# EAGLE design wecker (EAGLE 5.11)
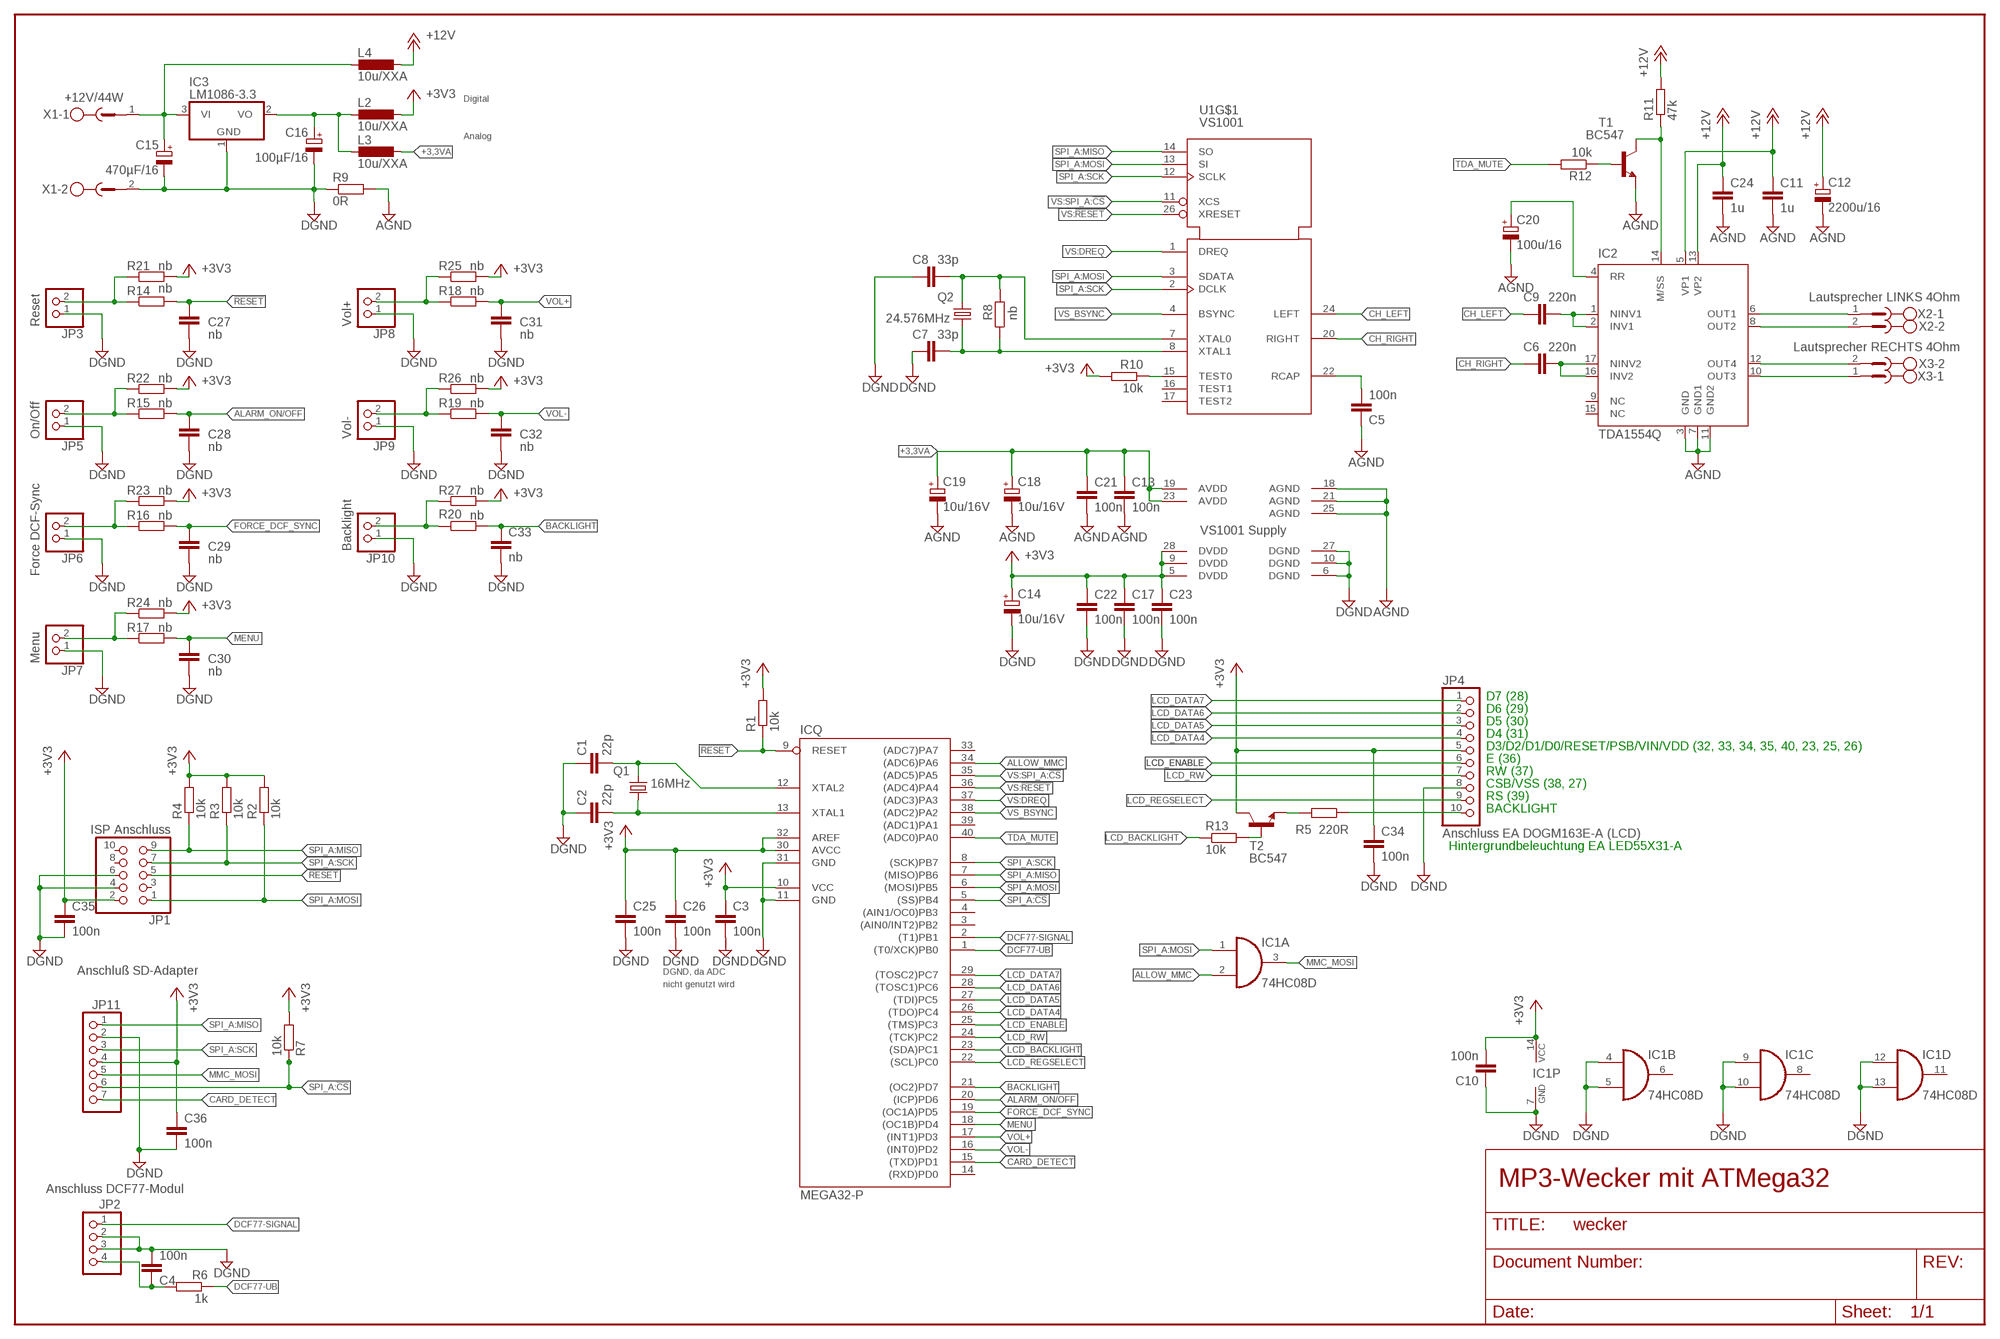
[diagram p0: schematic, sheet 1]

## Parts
C1  22p  C-EUC1206  [C1206]
C2  22p  C-EUC1206  [C1206]
C3  100n  C-EUC1206  [C1206]
C4  100n  C-EUC1206  [C1206]
C5  100n  C-EUC1206K  [C1206K]
C6  220n  C-EUC1206K  [C1206K]
C7  33p  C-EUC1206K  [C1206K]
C8  33p  C-EUC1206K  [C1206K]
C9  220n  C-EUC1206K  [C1206K]
C10  100n  C-EUC1206  [C1206]
C11  1u  C-EUC1206K  [C1206K]
C12  2200u/16  CPOL-EUE5-13  [E5-13]
C13  100n  C-EUC1206K  [C1206K]
C14  10u/16V  CPOL-EUE2,5-6E  [E2,5-6E]
C15  470µF/16  CPOL-EUE5-10.5  [E5-10,5]
C16  100µF/16  CPOL-EUE2,5-6E  [E2,5-6E]
C17  100n  C-EUC1206K  [C1206K]
C18  10u/16V  CPOL-EUE2,5-6E  [E2,5-6E]
C19  10u/16V  CPOL-EUE2,5-6E  [E2,5-6E]
C20  100u/16  CPOL-EUE2,5-6E  [E2,5-6E]
C21  100n  C-EUC1206K  [C1206K]
C22  100n  C-EUC1206K  [C1206K]
C23  100n  C-EUC1206K  [C1206K]
C24  1u  C-EUC1206K  [C1206K]
C25  100n  C-EUC1206  [C1206]
C26  100n  C-EUC1206  [C1206]
C27  nb  C-EUC1206K  [C1206K]
C28  nb  C-EUC1206K  [C1206K]
C29  nb  C-EUC1206K  [C1206K]
C30  nb  C-EUC1206K  [C1206K]
C31  nb  C-EUC1206K  [C1206K]
C32  nb  C-EUC1206K  [C1206K]
C33  nb  C-EUC1206K  [C1206K]
C34  100n  C-EUC1206K  [C1206K]
C35  100n  C-EUC1206K  [C1206K]
C36  100n  C-EUC1206K  [C1206K]
IC1  74HC08D  [SO14]
IC2  TDA1554Q  [MULTIWAT-SIL17]
IC3  LM1086-3.3  [TO220V]
ICQ  MEGA32-P  [DIL40]
JP1  ISP Anschluss  PINHD-2X5  [2X05]
JP2  Anschluss DCF77-Modul  PINHD-1X4  [1X04]
JP3  Reset  PINHD-1X2  [1X02]
JP4  Anschluss EA DOGM163E-A (LCD)  PINHD-1X10  [1X10]
JP5  On/Off  PINHD-1X2  [1X02]
JP6  Force DCF-Sync  PINHD-1X2  [1X02]
JP7  Menu  PINHD-1X2  [1X02]
JP8  Vol+  PINHD-1X2  [1X02]
JP9  Vol-  PINHD-1X2  [1X02]
JP10  Backlight  PINHD-1X2  [1X02]
JP11  Anschluß SD-Adapter  PINHD-1X7  [1X07]
L2  10u/XXA  L-EU0207/10  [0207/10]
L3  10u/XXA  L-EU0207/10  [0207/10]
L4  10u/XXA  L-EU0207/10  [0207/10]
Q1  16MHz  CRYSTALHC49S  [HC49/S]
Q2  24.576MHz  CRYSTALHC49S  [HC49/S]
R1  10k  R-EU_R1206  [R1206]
R2  10k  R-EU_R1206  [R1206]
R3  10k  R-EU_R1206  [R1206]
R4  10k  R-EU_R1206  [R1206]
R5  220R  R-EU_R1206  [R1206]
R6  1k  R-EU_R1206  [R1206]
R7  10k  R-EU_R1206  [R1206]
R8  nb  R-EU_R1206  [R1206]
R9  0R  R-EU_R1206  [R1206]
R10  10k  R-EU_R1206  [R1206]
R11  47k  R-EU_R1206  [R1206]
R12  10k  R-EU_R1206  [R1206]
R13  10k  R-EU_R1206  [R1206]
R14  nb  R-EU_R1206  [R1206]
R15  nb  R-EU_R1206  [R1206]
R16  nb  R-EU_R1206  [R1206]
R17  nb  R-EU_R1206  [R1206]
R18  nb  R-EU_R1206  [R1206]
R19  nb  R-EU_R1206  [R1206]
R20  nb  R-EU_R1206  [R1206]
R21  nb  R-EU_R1206  [R1206]
R22  nb  R-EU_R1206  [R1206]
R23  nb  R-EU_R1206  [R1206]
R24  nb  R-EU_R1206  [R1206]
R25  nb  R-EU_R1206  [R1206]
R26  nb  R-EU_R1206  [R1206]
R27  nb  R-EU_R1206  [R1206]
T1  BC547  [TO92]
T2  BC547  [TO92]
U1  VS1001-SOIC-28  [SO-28L]
X1  +12V/44W  MSTBV2  [MSTBV2]
X2  Lautsprecher LINKS 4Ohm  MSTBV2  [MSTBV2]
X3  Lautsprecher RECHTS 4Ohm  MSTBV2  [MSTBV2]

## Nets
!RESET: C27.1 ICQ.9(RESET) JP1.5 R1.1 R14.2
+3,3VA: C13.1 C18.+ C19.+ C21.1 L3.1 U1.19(AVDD) U1.23(AVDD)
+3V3: C3.1 C10.2 C14.+ C17.1 C22.1 C23.1 C25.1 C26.1 C34.1 C35.1 C36.1 IC1.14(P:VCC) ICQ.10(VCC) ICQ.30(AVCC) ICQ.32(AREF) JP1.2 JP4.5 JP11.4 L2.1 R1.2 R2.2 R3.2 R4.2 R7.2 R10.2 R21.2 R22.2 R23.2 R24.2 R25.2 R26.2 R27.2 T2.3(C) U1.5(DVDD) U1.9(DVDD) U1.28(DVDD)
+12V: C11.1 C12.+ C24.1 IC2.5(VP1) IC2.13(VP2) L4.1 R11.2
+UB: C4.1 JP2.4 R6.2
AGND: C5.1 C11.2 C12.- C13.2 C18.- C19.- C20.- C21.2 C24.2 IC2.3(GND) IC2.7(GND1) IC2.11(GND2) R9.2 T1.1(E) U1.18(AGND) U1.21(AGND) U1.25(AGND)
ALARM_ON/OFF: C28.1 ICQ.20((ICP)PD6) R15.2
ALLOW_MMC: IC1.2(A:I1) ICQ.34((ADC6)PA6)
BACKLIGHT: C33.1 ICQ.21((OC2)PD7) R20.2
BKL: R13.2 T2.2(B)
BKLIGHT: JP4.10 R5.1
CARD_DETECT: ICQ.15((TXD)PD1) JP11.7
CH_LEFT: C9.1 U1.24(LEFT)
CH_RIGHT: C6.1 U1.20(RIGHT)
DCF77-SIGNAL: ICQ.2((T1)PB1) JP2.1
DCF77-UB: ICQ.1((T0/XCK)PB0) R6.1
DGND: C1.1 C2.1 C3.2 C4.2 C7.1 C8.1 C10.1 C14.- C15.- C16.- C17.2 C22.2 C23.2 C25.2 C26.2 C27.2 C28.2 C29.2 C30.2 C31.2 C32.2 C33.2 C34.2 C35.2 C36.2 IC1.4(B:I0) IC1.5(B:I1) IC1.7(P:GND) IC1.9(C:I0) IC1.10(C:I1) IC1.12(D:I0) IC1.13(D:I1) IC3.1(GND) ICQ.11(GND) ICQ.31(GND) JP1.4 JP1.6 JP2.2 JP2.3 JP3.1 JP4.8 JP5.1 JP6.1 JP7.1 JP8.1 JP9.1 JP10.1 JP11.2 R9.1 U1.6(DGND) U1.10(DGND) U1.27(DGND) X1.2
FORCE_DCF_SYNC: C29.1 ICQ.19((OC1A)PD5) R16.2
INPUT_LEFT: C9.2 IC2.1(NINV1) IC2.2(INV1)
INPUT_RIGHT: C6.2 IC2.16(INV2) IC2.17(NINV2)
LCD_BACKLIGHT: ICQ.23((SDA)PC1) R13.1
LCD_DATA4: ICQ.26((TDO)PC4) JP4.4
LCD_DATA5: ICQ.27((TDI)PC5) JP4.3
LCD_DATA6: ICQ.28((TOSC1)PC6) JP4.2
LCD_DATA7: ICQ.29((TOSC2)PC7) JP4.1
LCD_ENABLE: ICQ.25((TMS)PC3) JP4.6
LCD_REGSELECT: ICQ.22((SCL)PC0) JP4.9
LCD_RW: ICQ.24((TCK)PC2) JP4.7
MENU: C30.1 ICQ.18((OC1B)PD4) R17.2
MMC_MOSI: IC1.3(A:O) JP11.5
MP3-TEST0: R10.1 U1.15(TEST0)
MP3-XTAL0: C8.2 Q2.2 R8.2 U1.7(XTAL0)
MP3-XTAL1: C7.2 Q2.1 R8.1 U1.8(XTAL1)
MUTE: IC2.14(M/SS) R11.1 T1.3(C)
N$1: C16.+ IC3.2(VO) L2.2 L3.2
N$2: C15.+ IC3.3(VI) L4.2 X1.1
N$3: R5.2 T2.1(E)
N$4: JP3.2 R14.1 R21.1
N$5: JP5.2 R15.1 R22.1
N$6: JP6.2 R16.1 R23.1
N$7: JP7.2 R17.1 R24.1
N$8: JP8.2 R18.1 R25.1
N$9: JP9.2 R19.1 R26.1
N$10: JP10.2 R20.1 R27.1
OUTPUT_LEFT1: IC2.6(OUT1) X2.1
OUTPUT_LEFT2: IC2.8(OUT2) X2.2
OUTPUT_RIGHT1: IC2.12(OUT4) X3.2
OUTPUT_RIGHT2: IC2.10(OUT3) X3.1
RCAP: C5.2 U1.22(RCAP)
RR: C20.+ IC2.4(RR)
SPI_A:!CS: ICQ.5((SS)PB4) JP11.6 R7.1
SPI_A:MISO: ICQ.7((MISO)PB6) JP1.9 JP11.1 R4.1 U1.14(SO)
SPI_A:MOSI: IC1.1(A:I0) ICQ.6((MOSI)PB5) JP1.1 R2.1 U1.3(SDATA) U1.13(SI)
SPI_A:SCK: ICQ.8((SCK)PB7) JP1.7 JP11.3 R3.1 U1.2(DCLK) U1.12(SCLK)
TDA_MUTE: ICQ.40((ADC0)PA0) R12.2
TDA_MUTE1: R12.1 T1.2(B)
VOL+: C31.1 ICQ.17((INT1)PD3) R18.2
VOL-: C32.1 ICQ.16((INT0)PD2) R19.2
VS:!RESET: ICQ.36((ADC4)PA4) U1.26(XRESET)
VS:DREQ: ICQ.37((ADC3)PA3) U1.1(DREQ)
VS:SPI_A:!CS: ICQ.35((ADC5)PA5) U1.11(XCS)
VS_BSYNC: ICQ.38((ADC2)PA2) U1.4(BSYNC)
XTAL1: C2.2 ICQ.13(XTAL1) Q1.2
XTAL2: C1.2 ICQ.12(XTAL2) Q1.1
Unconnected: IC1.6(B:O) IC1.8(C:O) IC1.11(D:O) IC2.9(NC) IC2.15(NC) ICQ.3((AIN0/INT2)PB2) ICQ.4((AIN1/OC0)PB3) ICQ.14((RXD)PD0) ICQ.33((ADC7)PA7) ICQ.39((ADC1)PA1) JP1.3 JP1.8 JP1.10 U1.16(TEST1) U1.17(TEST2)

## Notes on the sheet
- Digital
- Analog
- D7 (28)
- D6 (29)
- D5 (30)
- D4 (31)
- D3/D2/D1/D0/RESET/PSB/VIN/VDD (32, 33, 34, 35, 40, 23, 25, 26)
- E (36)
- RW (37)
- CSB/VSS (38, 27)
- RS (39)
- BACKLIGHT
- Hintergrundbeleuchtung EA LED55X31-A
- DGND, da ADC
- nicht genutzt wird
- MP3-Wecker mit ATMega32

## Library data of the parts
C1-C11 C13 C17 C21-C36 = rcl:C-EU: CAPACITOR, European symbol
C12 C14-C16 C18-C20 = rcl:CPOL-EU: POLARIZED CAPACITOR, European symbol
IC1 = 74xx-eu:74*08: Quad 2-input AND gate
IC2 = linear2:TDA1554Q: Audio Power Amplifier 4x11W single-ended or 2x22W BTL source: TDA1554Q_CNV.pdf
IC3 = oli:LM1086*: LM1086 1.5A Low Dropout Positive Regulators
ICQ = atmel:MEGA32-P: MICROCONTROLLER 32 Kbytes FLASH 2 Kbytes SRAM 1 Kbytes EEPROM USART 8-channel 10 bit ADC Source: www.atmel.com .. doc2503.pdf
JP1 = pinhead:PINHD-2X5: PIN HEADER
JP2 = pinhead:PINHD-1X4: PIN HEADER
JP3 JP5-JP10 = pinhead:PINHD-1X2: PIN HEADER
JP4 = pinhead:PINHD-1X10: PIN HEADER
JP11 = pinhead:PINHD-1X7: PIN HEADER
L2-L4 = rcl:L-EU: INDUCTOR, European symbol
Q1 Q2 = crystal:CRYSTAL: CRYSTAL
R1-R27 = rcl:R-EU_: RESISTOR, European symbol
T1 T2 = transistor:BC547: NPN TRANSISTOR
U1 = vs1001:VS1001: MP3 decoder chip from VLSI Solutions
X1-X3 = con-phoenix-500:MSTBV2: PHOENIX

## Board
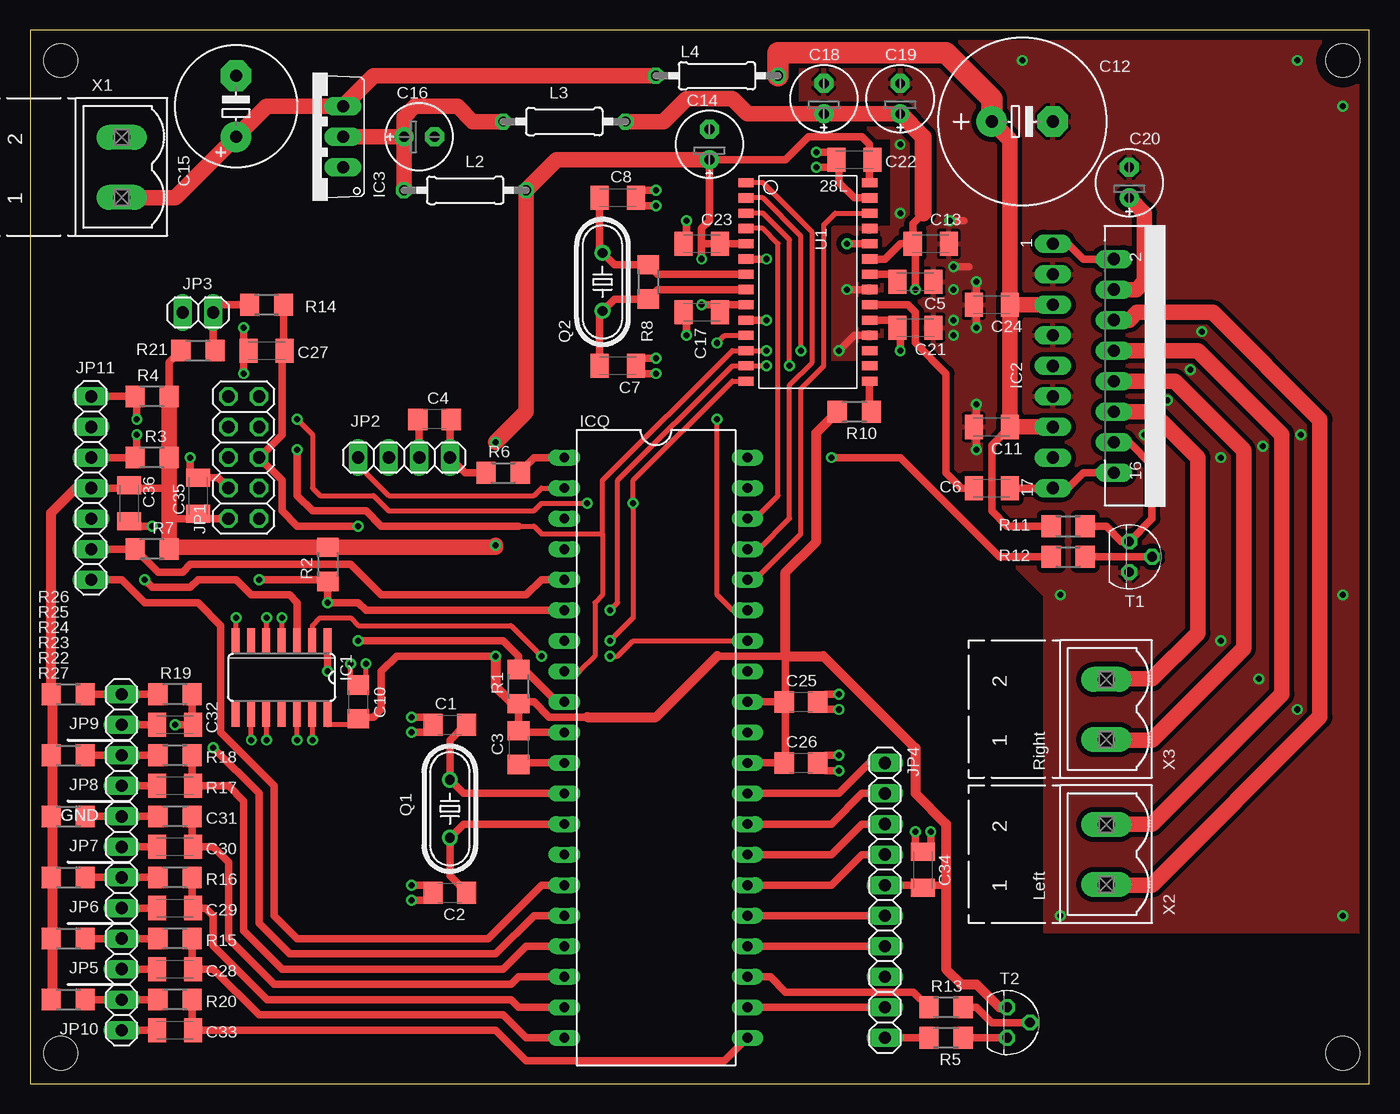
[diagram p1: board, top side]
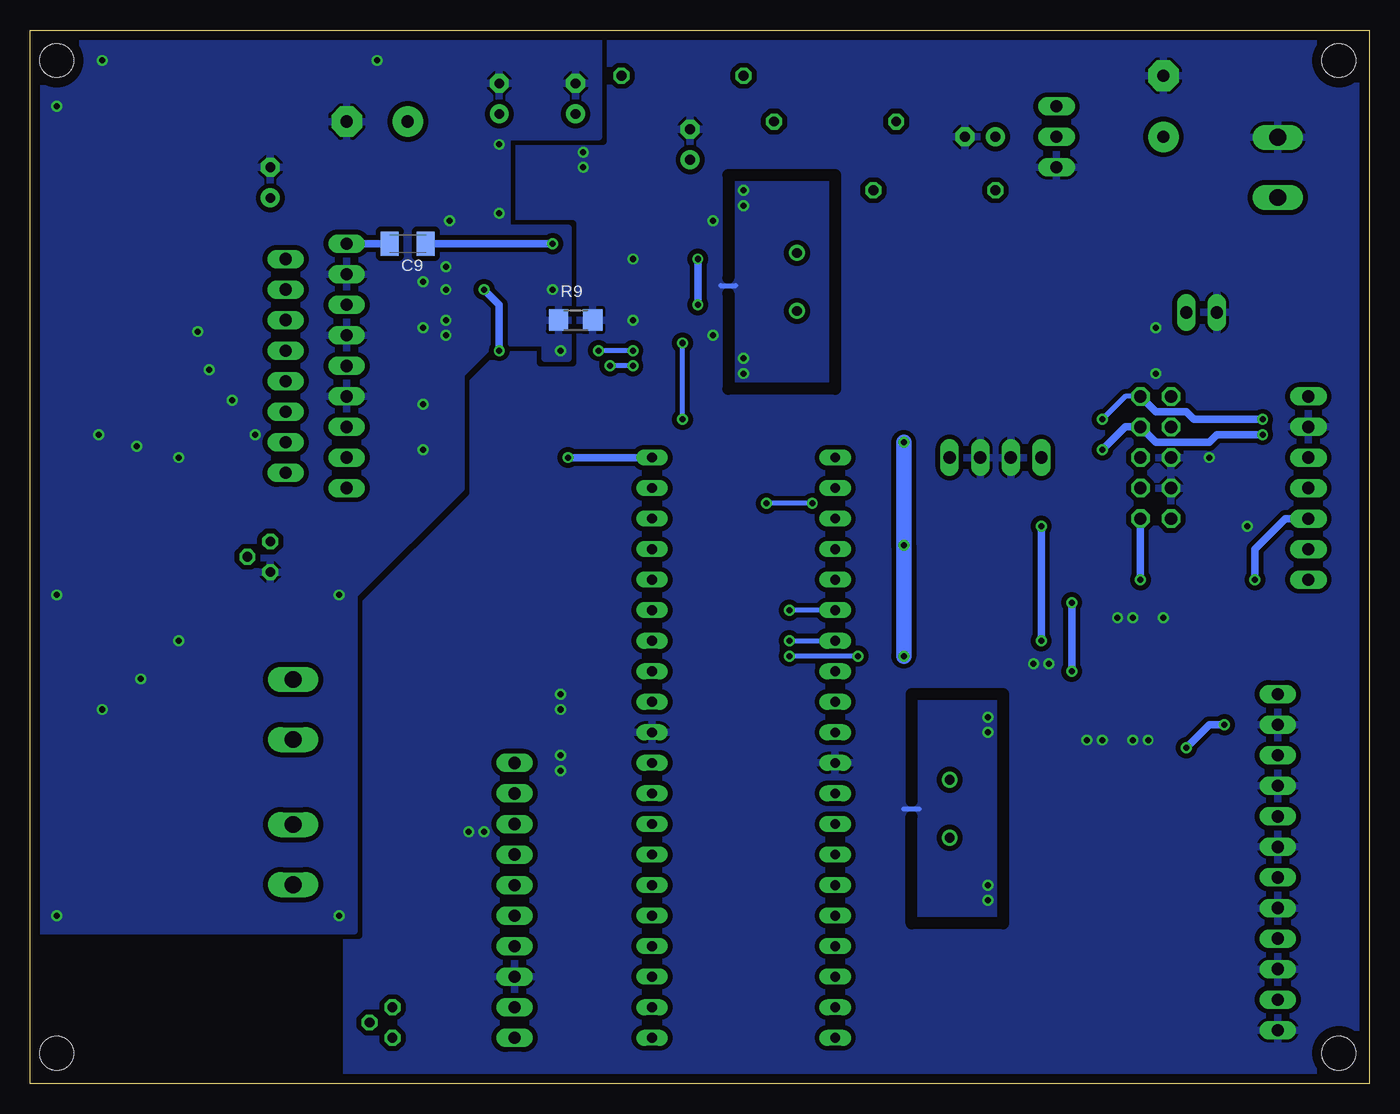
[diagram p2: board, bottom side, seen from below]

Size 111.43 x 87.62 mm. Coordinates in mm from the lower left corner, seen from the top.
Outline: 0,0 111.43,0 111.43,87.62 0,87.62 0,0
Copper layers (1*16): Top 0.035mm / dielectric 1.5mm / Bottom 0.035mm
Design rules "default *": minimum track width 16mil, minimum drill 19mil, track to track 16mil, track to pad 8mil, pad to pad 8mil, via to via 8mil, smd to smd 2mil, copper to edge 32mil, drill to drill 8mil, minimum pad ring 10mil, minimum via ring 8mil, stop-mask expansion 4mil, vias tented up to drill 20mil, thermal gap 10mil
Holes 2.8 mm at 109.22,2.54 109.22,85.09 2.54,85.09 2.54,2.54
bRestrict: 10 lines

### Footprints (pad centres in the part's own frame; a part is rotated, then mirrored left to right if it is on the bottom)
C1206 = smd 1.6 x 1.8: 1 -1.4,0; 2 1.4,0
C1206K = smd 1.5 x 2: 1 -1.5,0; 2 1.5,0
E5-13 = drill 1.016 pad 2.54 round: + -2.54,0 | drill 1.016 pad 2.54 octagon: - 2.54,0
E2,5-6E = drill 0.813 pad 1.575 round: + -1.27,0 | drill 0.813 pad 1.575 octagon: - 1.27,0
E5-10,5 = drill 1.016 pad 2.54 round: + -2.54,0 | drill 1.016 pad 2.54 octagon: - 2.54,0
SO14 = smd 0.66 x 2.032: 1 -3.81,-3.073; 2 -2.54,-3.073; 3 -1.27,-3.073; 4 0,-3.073; 5 1.27,-3.073; 6 2.54,-3.073; 7 3.81,-3.073; 8 3.81,3.073; 9 2.54,3.073; 10 1.27,3.073; 11 0,3.073; 12 -1.27,3.073; 13 -2.54,3.073; 14 -3.81,3.073
MULTIWAT-SIL17 = drill 1.016 long: 1 -10.16,-7.62; 2 -8.89,-2.54; 3 -7.62,-7.62; 4 -6.35,-2.54; 5 -5.08,-7.62; 6 -3.81,-2.54; 7 -2.54,-7.62; 8 -1.27,-2.54; 9 0,-7.62; 10 1.27,-2.54; 11 2.54,-7.62; 12 3.81,-2.54; 13 5.08,-7.62; 14 6.35,-2.54; 15 7.62,-7.62; 16 8.89,-2.54; 17 10.16,-7.62
TO220V = drill 1.016 long: 1 -2.54,-2.54; 2 0,-2.54; 3 2.54,-2.54
DIL40 = drill 0.813 long: 1 -24.13,-7.62; 2 -21.59,-7.62; 3 -19.05,-7.62; 4 -16.51,-7.62; 5 -13.97,-7.62; 6 -11.43,-7.62; 7 -8.89,-7.62; 8 -6.35,-7.62; 9 -3.81,-7.62; 10 -1.27,-7.62; 11 1.27,-7.62; 12 3.81,-7.62; 13 6.35,-7.62; 14 8.89,-7.62; 15 11.43,-7.62; 16 13.97,-7.62; 17 16.51,-7.62; 18 19.05,-7.62; 19 21.59,-7.62; 20 24.13,-7.62; 21 24.13,7.62; 22 21.59,7.62; 23 19.05,7.62; 24 16.51,7.62; 25 13.97,7.62; 26 11.43,7.62; 27 8.89,7.62; 28 6.35,7.62; 29 3.81,7.62; 30 1.27,7.62; 31 -1.27,7.62; 32 -3.81,7.62; 33 -6.35,7.62; 34 -8.89,7.62; 35 -11.43,7.62; 36 -13.97,7.62; 37 -16.51,7.62; 38 -19.05,7.62; 39 -21.59,7.62; 40 -24.13,7.62
2X05 = drill 1.016 octagon: 1 -5.08,-1.27; 2 -5.08,1.27; 3 -2.54,-1.27; 4 -2.54,1.27; 5 0,-1.27; 6 0,1.27; 7 2.54,-1.27; 8 2.54,1.27; 9 5.08,-1.27; 10 5.08,1.27
1X04 = drill 1.016 long: 1 -3.81,0; 2 -1.27,0; 3 1.27,0; 4 3.81,0
1X02 = drill 1.016 long: 1 -1.27,0; 2 1.27,0
1X10 = drill 1.016 long: 1 -11.43,0; 2 -8.89,0; 3 -6.35,0; 4 -3.81,0; 5 -1.27,0; 6 1.27,0; 7 3.81,0; 8 6.35,0; 9 8.89,0; 10 11.43,0
1X07 = drill 1.016 long: 1 -7.62,0; 2 -5.08,0; 3 -2.54,0; 4 0,0; 5 2.54,0; 6 5.08,0; 7 7.62,0
0207/10 = drill 0.813 octagon: 1 -5.08,0; 2 5.08,0
HC49/S = drill 0.813 round: 1 -2.413,0; 2 2.413,0
R1206 = smd 1.6 x 1.803: 1 -1.422,0; 2 1.422,0
TO92 = drill 0.813 octagon: 1 1.27,0; 2 0,1.905; 3 -1.27,0
SO-28L = smd 0.762 x 1.27: 1 -7.62,-5.207; 2 -6.35,-5.207; 3 -5.08,-5.207; 4 -3.81,-5.207; 5 -2.54,-5.207; 6 -1.27,-5.207; 7 0,-5.207; 8 1.27,-5.207; 9 2.54,-5.207; 10 3.81,-5.207; 11 5.08,-5.207; 12 6.35,-5.207; 13 7.62,-5.207; 14 8.89,-5.207; 15 8.89,5.08; 16 7.62,5.08; 17 6.35,5.08; 18 5.08,5.08; 19 3.81,5.08; 20 2.54,5.08; 21 1.27,5.08; 22 0,5.08; 23 -1.27,5.08; 24 -2.54,5.08; 25 -3.81,5.08; 26 -5.08,5.08; 27 -6.35,5.08; 28 -7.62,5.08
MSTBV2 = drill 1.397 long: 1 -2.5,0; 2 2.5,0

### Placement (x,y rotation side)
C1  34.93,29.84 0 top
C2  34.93,15.88 0 top
C3  40.64,27.94 270 top
C4  33.66,55.24 180 top
C5  73.66,66.68 180 top
C6  80.01,49.53 0 top
C7  48.9,59.69 180 top
C8  48.9,73.66 180 top
C9  80.01,69.85 180 bottom
C10  27.3,31.75 270 top
C11  80.01,54.61 180 top
C12  82.55,80.01 0 top
C13  74.93,69.85 0 top
C14  56.52,78.11 90 top
C15  17.14,81.28 90 top
C16  32.38,78.74 0 top
C17  55.88,64.14 180 top
C18  66.04,81.92 90 top
C19  72.39,81.92 90 top
C20  91.44,74.93 90 top
C21  73.66,62.87 0 top
C22  68.58,76.84 180 top
C23  55.88,69.85 180 top
C24  80.01,64.77 180 top
C25  64.14,31.75 0 top
C26  64.14,26.67 0 top
C27  19.68,60.96 180 top
C28  12.06,9.53 180 top
C29  12.06,14.61 180 top
C30  12.06,19.68 180 top
C31  12.06,24.77 180 top
C32  12.06,29.84 180 top
C33  12.06,4.45 180 top
C34  74.3,17.78 90 top
C35  13.97,48.89 90 top
C36  8.26,48.26 270 top
IC1  20.93,33.78 180 top
IC2  92.71,59.69 270 top
IC3  23.5,78.74 90 top
ICQ  52.07,27.94 270 top
JP1  17.78,52.07 90 top
JP2  31.11,52.07 0 top
JP3  13.97,64.14 0 top
JP4  71.12,15.24 270 top
JP5  7.62,10.8 90 top
JP6  7.62,15.88 90 top
JP7  7.62,20.95 90 top
JP8  7.62,26.04 90 top
JP9  7.62,31.11 90 top
JP10  7.62,5.71 90 top
JP11  5.08,49.53 270 top
L2  36.2,74.3 180 top
L3  44.45,80.01 180 top
L4  57.15,83.82 180 top
Q1  34.93,22.86 270 top
Q2  47.62,66.68 90 top
R1  40.64,33.02 270 top
R2  24.77,43.18 90 top
R3  10.16,52.07 0 top
R4  10.16,57.15 0 top
R5  76.2,3.81 0 top
R6  39.37,50.8 180 top
R7  10.16,44.45 0 top
R8  51.44,66.68 90 top
R9  66.04,63.5 180 bottom
R10  68.58,55.88 180 top
R11  86.36,46.35 180 top
R12  86.36,43.81 180 top
R13  76.2,6.35 0 top
R14  19.68,64.77 0 top
R15  12.06,12.07 0 top
R16  12.06,17.14 0 top
R17  12.06,22.22 0 top
R18  12.06,27.3 0 top
R19  12.06,32.38 0 top
R20  12.06,6.99 0 top
R21  13.97,60.96 180 top
R22  3.17,12.07 180 top
R23  3.17,17.14 180 top
R24  3.17,22.22 180 top
R25  3.17,27.3 180 top
R26  3.17,32.38 180 top
R27  3.17,6.99 180 top
T1  91.44,43.81 270 top
T2  81.28,5.08 270 top
U1  64.77,67.31 270 top
X1  7.62,76.2 90 top
X2  89.53,19.05 90 top
X3  89.53,31.11 90 top

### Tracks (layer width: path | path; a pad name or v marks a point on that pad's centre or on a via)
!RESET  (via drill 0.5)
  Top 0.61: ICQ.9 43.82,31.75 41.28,34.29 R1.1 40.64,35.56 39.37,36.83 v27.3,36.83 | v27.3,46.35 22.22,46.35 20.95,47.62 20.95,50.16 JP1.5 20.95,53.98 20.95,60.73 C27.1 21.11,61.04 R14.2
  Bottom 0.61: v27.3,36.83 v27.3,46.35
+3,3VA  (via drill 0.5)
  Top 0.61: C13.1 72.39,69.85 71.12,68.58 U1.23 | U1.19 71.75,63.5 72.39,62.87 C21.1 72.16,62.46 72.39,62.23 v72.39,60.96 | 74.3,72.39 73.43,71.53 C13.1 | C13.1 73.66,69.62 v73.66,66.04
  Top 1.27: L3.1 52.71,80.01 54.61,81.92 58.42,81.92 59.69,80.65 C18.+ C19.+
  Top 1.422: C19.+ 74.3,78.74 74.3,72.39
  Bottom 0.61: v73.66,66.04 72.39,64.77 v72.39,60.96
+3V3  (via drill 0.5)
  Top 0.406: C10.2 27.3,29.84 24.77,29.84 24.74,29.87 IC1.14
  Top 0.61: C23.1 U1.5 | 57.38,64.77 U1.9 | 57.38,64.77 C17.1 | ICQ.10 41.41,29.21 C3.1 R1.2 | 57.15,35.56 62.87,35.56 62.87,31.88 C25.1 | ICQ.30 C26.1 62.87,26.8 62.87,31.62 C25.1 | C25.1 ICQ.32 | 55.88,69.85 55.88,71.12 56.52,71.76 C14.+ 62.87,76.84 64.77,78.74 69.21,78.74 69.85,78.11 69.85,77.07 C22.1 | 55.88,69.85 C23.1 | C23.1 57.15,69.62 | 57.38,64.77 57.15,64.54 57.15,64.77 v55.88,64.77 | 55.88,69.85 v55.88,68.58 | C22.1 70.08,77.24 | U1.28 69.85,76.61 C22.1 | 46.36,30.48 43.18,30.48 41.91,31.75 40.79,31.75 R1.2 | R1.2 40.64,31.75 40.01,31.75 | v38.74,35.56 30.48,35.56 29.21,34.29 29.21,31.11 28.57,30.48 27.43,30.48 C10.2 | R4.2 11.58,59.99 R21.2 | JP11.4 8.03,49.53 C36.1 8.48,49.53 11.58,49.53 | JP1.2 14.38,46.99 C35.1 13.97,46.99 11.58,46.99 | 76.2,16.51 74.52,16.51 C34.1 74.06,16.51 JP4.5
  Top 0.813: T2.3 80.64,6.35 78.74,8.25 77.47,8.25 76.2,9.53 76.2,16.51 76.2,21.59 73.66,24.13 73.66,27.9 66,35.56 62.87,35.56 62.87,42.55 65.41,45.09 65.41,54.13 R10.2 | 57.15,35.56 52.07,30.48 46.36,30.48 | v38.74,35.56 38.74,33.02 40.01,31.75 | R27.2 1.91,6.99 1.91,12.07 | 1.91,12.07 R22.2 | 1.91,12.07 1.91,17.14 | 1.91,17.14 R23.2 | 1.91,17.14 1.91,22.22 | 1.91,22.22 R24.2 | 1.91,22.22 1.91,27.3 | 1.91,27.3 R25.2 | 1.91,27.3 1.91,32.38 R26.2 1.75,47.47 3.81,49.53 JP11.4
  Top 1.27: C14.+ 43.82,76.84 L2.1 41.28,55.88 v38.74,53.34 | R4.2 R3.2 11.58,49.53 11.58,46.99 R7.2 11.73,44.6 R2.2 38.74,44.6 v38.74,44.77
  Bottom 0.61: v55.88,68.58 v55.88,64.77
  Bottom 1.27: v38.74,53.34 v38.74,44.77 v38.74,35.56
+12V
  Top 0.61: R11.2 81.28,46.35 80.01,47.62 80.01,53.11 C11.1
  Top 1.27: C24.1 IC2.5 | IC2.13 C11.1 C24.1 | C24.1 81.51,78.51 C12.+
  Top 1.778: C12.+ 80.01,81.92 76.2,85.73 62.23,85.73 L4.1
+UB
  Top 0.61: R6.2 36.2,50.8 JP2.4 34.93,55.12 C4.1
AGND  (via drill 0.5)
  Top 0.61: v78.74,62.87 78.74,64.54 C24.2 78.74,65 v78.74,66.68 | v78.74,56.52 78.74,54.84 C11.2 78.74,54.38 v78.74,52.7 | v67.94,66.04 U1.21 | v76.52,71.76 77.7,71.76 | 77.06,67.95 78.1,67.95 | U1.18 68.58,62.23 v67.31,60.96
  other vias: 72.39,72.39 76.83,67.95 76.83,66.04 76.83,63.5 76.83,62.23 72.39,78.11 94.61,56.83 96.52,59.37 97.47,62.55 105.73,53.98 102.55,53.02 99.06,52.07 92.71,53.98 109.22,13.97 85.72,13.97 85.72,40.64 109.22,40.64 109.22,81.28 105.41,85.09 82.55,85.09 102.23,33.66 99.06,36.83 105.41,31.11
  pour Bottom (isolate 0.305): 64.14,78.74 71.75,78.74 71.75,71.12 66.67,71.12 66.67,60.32 68.58,60.32 68.58,61.59 72.95,61.59 75.56,58.98 75.56,49.53 84.45,40.64 84.45,12.7 111.76,12.7 111.76,87.63 64.14,87.63
  pour Top (isolate 0.406): 64.14,87.63 64.14,78.74 71.75,78.74 71.75,71.12 66.67,71.12 66.67,60.32 68.58,60.32 68.58,61.59 73.02,61.59 75.56,59.05 75.56,49.53 84.45,40.64 84.45,12.7 111.76,12.7 111.76,87.63
ALARM_ON/OFF
  Top 0.61: ICQ.20 41.28,3.81 39.37,5.71 19.05,5.71 15.24,9.53 C28.1 13.49,9.6 R15.2
ALLOW_MMC  (via drill 0.5)
  Top 0.406: ICQ.34 50.17,36.83 48.9,35.56 v48.26,35.56 | v42.55,35.56 40.01,38.1 27.3,38.1 26.67,38.73 24.13,38.73 23.5,38.1 23.5,36.88 IC1.2
  Bottom 0.406: v42.55,35.56 v48.26,35.56
BACKLIGHT
  Top 0.61: ICQ.21 57.79,1.91 41.28,1.91 38.74,4.45 C33.1 13.49,4.52 R20.2
BKL
  Top 0.61: R13.2 78.74,6.35 80.01,5.08 T2.2
BKLIGHT
  Top 0.61: JP4.10 R5.1
CARD_DETECT
  Top 0.61: ICQ.15 42.55,16.51 38.1,12.07 22.22,12.07 20.32,13.97 20.32,24.77 15.88,29.21 15.88,38.1 13.97,40.01 9.53,40.01 7.62,41.91 JP11.7
CH_LEFT  (via drill 0.5)
  Top 0.61: v67.94,69.85 U1.24
  Bottom 0.61: v67.94,69.85 C9.1
CH_RIGHT
  Top 0.61: U1.20 73.02,64.77 73.66,64.14 73.66,61.59 76.2,59.05 76.2,50.8 77.47,49.53 C6.1
DCF77-SIGNAL
  Top 0.406: JP2.1 27.3,51.44 29.84,48.89 41.91,48.89 42.55,49.53 ICQ.2
DCF77-UB
  Top 0.61: R6.1 40.79,50.95 41.91,52.07 ICQ.1
DGND  (via drill 0.5)
  Top 0.406: IC1.7 17.14,36.88 v17.14,38.73 | IC1.5 19.68,36.88 v19.68,38.73 | IC1.4 20.95,36.88 v20.95,38.73 | IC1.10 19.68,30.68 v19.68,28.57 | IC1.9 18.41,30.68 v18.41,28.57 | IC1.12 22.22,30.68 v22.22,28.57 | IC1.13 23.5,30.68 v23.5,28.57 | v26.67,34.92 26.67,33.79 C10.1 27.94,33.79 v27.94,34.92
  Top 0.61: v31.75,30.48 32.89,30.48 C1.1 32.89,29.21 v31.75,29.21 | v31.75,16.51 32.89,16.51 C2.1 32.89,15.24 v31.75,15.24 | v52.07,74.3 51.03,74.3 C8.1 51.03,73.03 v52.07,73.03 | v52.07,60.32 51.03,60.32 C7.1 51.03,59.05 v52.07,59.05 | v54.61,71.76 54.61,70.08 C23.2 54.61,69.62 | 54.61,63.73 C17.2 54.61,64.54 54.61,63.73 | 54.61,63.73 v54.61,62.23 | v67.31,32.38 66.17,32.38 C25.2 66.17,31.11 v67.31,31.11 | v67.31,27.3 66.17,27.3 C26.2 66.17,26.04 v67.31,26.04 | U1.27 68.58,73.66 67.31,74.93 67.31,76.61 | 67.31,76.61 C22.2 66.44,77.47 v65.41,77.47 | 67.31,76.61 66.91,76.2 v65.41,76.2 | U1.6 v61.28,68.58 | U1.10 v61.28,63.5 | C3.2 41.41,26.67 ICQ.11 | C4.2 32.38,55.12 JP2.3 | JP10.1 C33.2 | JP5.1 C28.2 | JP6.1 C29.2 | JP7.1 C30.2 | JP9.1 C32.2 | v17.78,59.05 17.78,60.55 C27.2 17.78,61.37 v17.78,62.87 | 10.79,24.99 C31.2 JP8.1 | C36.2 8.66,46.35 v10.16,46.35 | JP1.4 15.64,50.39 C35.2 13.33,51.03 v13.33,52.07 | v73.66,20.95 73.66,19.91 C34.2 74.93,19.91 v74.93,20.95
  Bottom 0.406: 53.98,66.36 52.71,66.36 | 38.74,22.86 37.47,22.86
  pour Bottom (isolate 0.305, rank 2): 0,87.63 0,0 85.09,0 85.09,87.63
FORCE_DCF_SYNC
  Top 0.61: ICQ.19 40.64,6.35 40.01,6.99 19.73,6.99 15.24,11.48 15.24,13.97 14.61,14.61 C29.1 13.49,14.68 R16.2
INPUT_LEFT
  Top 0.61: IC2.1 86.36,69.85 87.63,68.58 IC2.2
  Bottom 0.61: C9.2 IC2.1
INPUT_RIGHT
  Top 0.61: IC2.16 87.63,50.8 86.36,49.53 IC2.17 C6.2
LCD_BACKLIGHT
  Top 0.61: ICQ.23 61.6,8.89 62.87,7.62 73.51,7.62 R13.1
LCD_DATA4
  Top 0.61: ICQ.26 66.67,16.51 69.21,19.05 JP4.4
LCD_DATA5
  Top 0.61: ICQ.27 66.67,19.05 69.21,21.59 JP4.3
LCD_DATA6
  Top 0.61: ICQ.28 66.67,21.59 69.21,24.13 JP4.2
LCD_DATA7
  Top 0.61: ICQ.29 67.31,24.13 69.85,26.67 JP4.1
LCD_ENABLE
  Top 0.61: ICQ.25 JP4.6
LCD_REGSELECT
  Top 0.61: ICQ.22 JP4.9
LCD_RW
  Top 0.61: ICQ.24 JP4.7
MENU
  Top 0.61: ICQ.18 40.64,8.89 40.01,8.25 20.32,8.25 16.51,12.07 16.51,18.41 15.24,19.68 C30.1 13.49,19.76 R17.2
MMC_MOSI  (via drill 0.5)
  Top 0.61: IC1.3 22.22,36.88 22.22,40.01 21.59,40.64 18.41,40.64 17.14,41.91 13.97,41.91 13.33,41.27 10.16,41.27 v9.53,41.91
  Bottom 0.61: v9.53,41.91 9.53,44.45 6.98,46.99 JP11.5
MP3-TEST0
  Top 0.61: U1.15 69.85,56.03 R10.1
MP3-XTAL0
  Top 0.61: U1.7 52.22,67.31 R8.2 48.62,68.1 Q2.2 47.4,69.32 C8.2
MP3-XTAL1
  Top 0.406: 47.4,64.03 Q2.1
  Top 0.61: U1.8 52.22,66.04 R8.1 48.62,65.25 Q2.1 | C7.2 47.4,64.03
MUTE
  Top 0.61: IC2.14 91.44,53.34 93.34,51.44 93.34,46.99 T1.3 90.8,45.09 89.53,46.35 R11.1
N$1
  Top 1.27: L2.2 C16.+ | C16.+ 31.11,80.38 32.01,81.28 35.56,81.28 36.83,80.01 L3.2 | C16.+ IC3.2
N$2
  Top 1.27: L4.2 28.57,83.82 IC3.3 19.68,81.28 C15.+ 12.06,73.66 7.66,73.66 X1.1
N$3
  Top 0.61: R5.2 T2.1
N$4
  Top 0.61: R21.1 15.24,61.11 JP3.2 15.88,64.77 R14.1
N$5
  Top 0.61: R22.1 JP5.2 R15.1
N$6
  Top 0.61: R23.1 JP6.2 R16.1
N$7
  Top 0.61: R24.1 JP7.2 R17.1
N$8
  Top 0.61: R25.1 JP8.2 R18.1
N$9
  Top 0.61: R19.1 JP9.2 R26.1
N$10
  Top 0.61: R27.1 JP10.2 R20.1
OUTPUT_LEFT1
  Top 1.27: IC2.6 91.44,63.5 92.08,64.14 98.4,64.14 107.31,55.22 107.31,30.49 93.33,16.51 90.17,16.51 X2.1
OUTPUT_LEFT2
  Top 1.27: IC2.8 97.16,60.96 104.14,53.98 104.14,32.38 93.34,21.59 90.17,21.59 X2.2
OUTPUT_RIGHT1
  Top 1.27: IC2.12 93.34,55.88 97.16,52.07 97.16,37.46 93.34,33.66 90.17,33.66 X3.2
OUTPUT_RIGHT2
  Top 1.27: IC2.10 95.22,58.42 100.96,52.67 100.96,36.2 93.34,28.57 90.17,28.57 X3.1
RCAP
  Top 0.61: U1.22 71.75,67.31 C5.2
RR
  Top 1.27: IC2.4 92.03,66.04 92.71,66.72 92.71,72.39 C20.+
SPI_A:!CS
  Top 0.61: JP11.6 R7.1 10.64,42.55 12.7,42.55 13.33,43.18 26.67,43.18 29.21,40.64 41.28,40.64 42.55,41.91 ICQ.5
SPI_A:MISO  (via drill 0.5)
  Top 0.406: v48.26,36.83 50.17,38.73 v50.17,48.26 50.17,50.16 58.42,58.42 U1.14 | v22.22,55.24 23.5,53.98 23.5,49.53 24.13,48.89 28.57,48.89 29.84,47.62 41.91,47.62 42.55,48.26 v46.36,48.26
  Top 0.61: v8.89,55.24 8.89,57.15 R4.1 JP11.1
  Bottom 0.406: v48.26,36.83 ICQ.7 | JP1.9 20.32,57.15 v22.22,55.24 | v46.36,48.26 v50.17,48.26
  Bottom 0.61: JP1.9 17.78,55.88 15.24,55.88 14.61,55.24 v8.89,55.24
SPI_A:MOSI  (via drill 0.5)
  Top 0.406: v63.18,59.69 63.18,70.17 60.96,72.39 U1.3 | v61.28,59.69 U1.13 58.42,59.69 48.9,50.16 48.9,40.01 v48.26,39.37
  Top 0.61: v24.77,34.29 24.77,36.83 IC1.1 | ICQ.6 27.94,39.37 27.3,40.01 v24.77,40.01 R2.1 24.61,41.27 24.77,41.91 v19.05,41.91
  Bottom 0.406: v61.28,59.69 v63.18,59.69 | ICQ.6 v48.26,39.37
  Bottom 0.61: v24.77,34.29 v24.77,40.01 | v19.05,41.91 JP1.1
SPI_A:SCK  (via drill 0.5)
  Top 0.406: v64.14,60.96 64.14,70.48 60.96,73.66 U1.2 | v61.28,60.96 U1.12 58.42,60.96 47.62,50.16 47.62,45.72 | ICQ.8 45.72,34.29 46.99,35.56 46.99,40.01 47.62,40.64 47.62,45.72 | 40.64,46.35 41.91,46.35 42.55,45.72 47.62,45.72
  Top 0.61: v8.89,53.98 8.89,52.22 R3.1 JP11.3 | v22.22,52.7 22.22,48.89 23.5,47.62 27.94,47.62 29.21,46.35 40.64,46.35
  Bottom 0.406: v61.28,60.96 v64.14,60.96
  Bottom 0.61: v8.89,53.98 12.7,53.98 13.33,53.34 17.78,53.34 JP1.7 20.32,54.61 v22.22,52.7
TDA_MUTE  (via drill 0.5)
  Top 0.61: v66.67,52.07 72.39,52.07 80.64,43.81 R12.2
  Bottom 0.61: ICQ.40 v66.67,52.07
TDA_MUTE1
  Top 0.61: R12.1 T1.2
VOL+
  Top 0.61: ICQ.17 41.28,11.43 39.37,9.53 20.99,9.53 17.78,12.73 17.78,23.49 16.51,24.77 C31.1 13.49,24.84 R18.2
VOL-  (via drill 0.5)
  Top 0.61: ICQ.16 41.91,13.97 38.74,10.8 21.59,10.8 19.05,13.34 19.05,24.13 v15.24,27.94 | v12.06,29.84 C32.1 13.49,29.92 R19.2
  Bottom 0.61: v12.06,29.84 13.33,29.84 v15.24,27.94
VS:!RESET
  Top 0.406: U1.26 66.99,72.39 66.04,71.44 66.04,59.69 64.14,57.78 64.14,45.72 60.33,41.91 ICQ.36
VS:DREQ
  Top 0.406: U1.1 60.96,74.93 65.09,70.8 65.09,60.01 63.18,58.1 63.18,47.01 60.62,44.45 ICQ.37
VS:SPI_A:!CS  (via drill 0.5)
  Top 0.406: v57.15,61.59 57.79,62.23 U1.11 | v57.15,55.24 57.15,40.64 58.42,39.37 ICQ.35
  Bottom 0.406: v57.15,55.24 v57.15,61.59
VS_BSYNC
  Top 0.406: U1.4 60.96,71.12 62.23,69.85 62.23,48.89 60.33,46.99 ICQ.38
XTAL1
  Top 0.406: 34.93,20.32 Q1.2
  Top 0.61: ICQ.13 36.07,21.59 Q1.2 | 34.93,20.32 34.93,17.27 C2.2
XTAL2
  Top 0.406: 36.2,29.84 36.2,29.71 C1.2
  Top 0.61: ICQ.12 36.07,24.13 Q1.1 34.93,28.57 36.2,29.84

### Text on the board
Unrouted: DGND | AGND | +12V | 1 | AGND | 1 | DGND | 1
tNames: Right | GND | GND | Left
